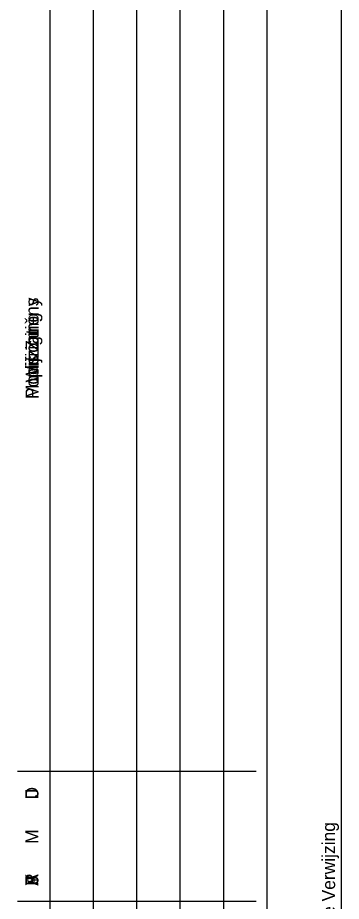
# Model space of a CAD drawing. Extents: x -932963 to -932666, y -737039 to -736000.
# Drawn here: x -932796.5886 to -932796.57, y -736668.9905 to -736668.9396 of the extents above; entities that cross this region are included whole.
import ezdxf

# ---------------------------------------------------------------- set-up
doc = ezdxf.new("R2010")
doc.units = 0
for name, color, linetype in [('Border', 7, 'Continuous'), ('Border_TextCZ', 7, 'Continuous'), ('Border_TextFR', 7, 'Continuous'), ('Border_TextNL', 7, 'Continuous'), ('Border_TextUK', 7, 'Continuous')]:
    doc.layers.add(name, color=color, linetype=linetype)

# ---------------------------------------------------------------- blocks, each defined once
blk = doc.blocks.new('A0_v03_CZ_1')
at = {"layer": 'Border'}
blk.add_line((0.98758, 0.15206), (1.17758, 0.15206), dxfattribs=at)
for points in [[(0.99542, 0.15581), (0.99542, 0.12831)], [(1.01042, 0.15581), (1.01042, 0.12831)], [(0.98758, 0.15206), (1.17842, 0.15206)], [(0.98758, 0.14706), (1.17842, 0.14706)], [(0.98758, 0.14206), (1.17842, 0.14206)], [(0.98758, 0.13706), (1.17842, 0.13706)], [(0.98758, 0.13206), (1.17842, 0.13206)], [(0.98758, 0.12706), (1.17842, 0.12706)], [(0.98758, 0.1185), (1.17842, 0.1185)]]:
    blk.add_lwpolyline(points, dxfattribs=at)
at = {"layer": 'Border_TextCZ'}
for s, p in [('R', (0.99721, 0.15341)), ('M', (1.00204, 0.15341)), ('D', (1.00715, 0.15341)), ('Popis Změny', (1.0533, 0.1534))]:
    blk.add_text(s, height=0.0015, dxfattribs=at).set_placement(p)
at = {"layer": 'Border_TextFR'}
for s, p in [('A', (0.99721, 0.15341)), ('M', (1.00204, 0.15341)), ('J', (1.00739, 0.15341)), ('Modifications', (1.0533, 0.1534))]:
    blk.add_text(s, height=0.0015, dxfattribs=at).set_placement(p)
at = {"layer": 'Border_TextNL'}
for s, p in [('J', (0.99739, 0.15341)), ('M', (1.00204, 0.15341)), ('D', (1.00715, 0.15341)), ('Wijziging', (1.05522, 0.1534)), ('Externe Verwijzing', (0.98794, 0.11922))]:
    blk.add_text(s, height=0.0015, dxfattribs=at).set_placement(p)
at = {"layer": 'Border_TextUK'}
for s, p in [('Y', (0.99721, 0.15341)), ('M', (1.00204, 0.15341)), ('D', (1.00715, 0.15341)), ('Modifications', (1.0533, 0.1534))]:
    blk.add_text(s, height=0.0015, dxfattribs=at).set_placement(p)

msp = doc.modelspace()

# ---------------------------------------------------------------- block references
at = {"layer": 'Border', "xscale": 0.5, "yscale": 0.5, "rotation": 90}
msp.add_blockref('A0_v03_CZ_1', (-932796.510744, -736669.488249), dxfattribs=at)

doc.saveas('drawing.dxf')
